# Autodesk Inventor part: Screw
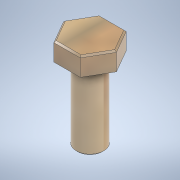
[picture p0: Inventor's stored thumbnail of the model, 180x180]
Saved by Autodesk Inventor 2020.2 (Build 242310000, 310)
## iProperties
Created: 2020-01
Part Number: Screw
Material: Wood (Maple)
Document SubType Name: Modeling
Designer: thira
Density: 0.67 g/cm^3
Appearance: Natural Maple - Glossy Dark Tint
Author: thira
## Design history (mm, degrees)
sketch "Sketch1"
  geometry: L1 (8.66, 0)-(4.33, -7.5); L2 (4.33, -7.5)-(-4.33, -7.5); L3 (-4.33, -7.5)-(-8.66, 0); L4 (-8.66, 0)-(-4.33, 7.5); L5 (-4.33, 7.5)-(4.33, 7.5); L6 (4.33, 7.5)-(8.66, 0); C1 r 4.5 at (0, 0); 2 further points
  constraints: 12 end point, 2 coincident, 1 centre point, 1 horizontal alignment, 13 other
  dimensions: "d0" = 15 distance between parallel lines of L2 L5; "d1" = 9 diameter of C1
extrude "Extrusion1" new body sketch "Sketch1" distance "d2" = 6; taper "d3" = 0 deg
extrude "Extrusion2" join sketch "Sketch1" distance "d4" = 25; taper "d5" = 0 deg
chamfer "Chamfer1" distance "d6" = 0.5; stored, may be unused: second distance "d7" = 2, angle "d8" = 45 deg
chamfer "Chamfer2" distance "d9" = 0.5; stored, may be unused: second distance "d10" = 2, angle "d11" = 45 deg
body "Solid1"
